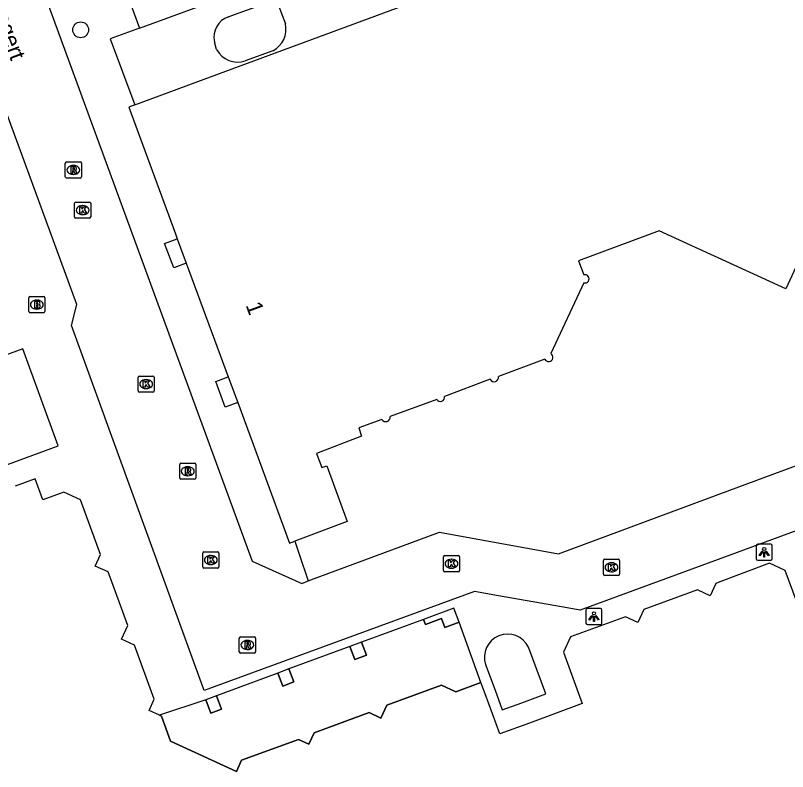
# Model space of a CAD drawing. Extents: x 160806 to 161707, y 383697 to 384148.
# Drawn here: x 160956.33 to 161004.31, y 383874.79 to 383921.78 of the extents above; entities that cross this region are included whole.
import ezdxf

# ---------------------------------------------------------------- set-up
doc = ezdxf.new("R2010")
doc.units = 0
for name, color, linetype in [('IMGEO_Boom', 7, 'Continuous'), ('IMGEO_Brandkraan', 7, 'Continuous'), ('IMGEO_Kolk', 7, 'Continuous'), ('IMGEO_Lichtpunt', 7, 'Continuous'), ('IMGEO_Openbare_ruimte_label', 7, 'Continuous'), ('IMGEO_Pand', 7, 'Continuous'), ('IMGEO_Pand_nummerreeks', 7, 'Continuous'), ('IMGEO_Pand_overbouw', 7, 'Continuous'), ('IMGEO_Rijbaan_lokaal_open', 7, 'Continuous'), ('IMGEO_Rioolput', 7, 'Continuous'), ('IMGEO_Voetpad_open', 7, 'Continuous')]:
    doc.layers.add(name, color=color, linetype=linetype)

msp = doc.modelspace()

# ---------------------------------------------------------------- linework, layer by layer
at = {"layer": 'IMGEO_Boom'}
msp.add_circle((160960.386, 383920.883), 0.489, dxfattribs=at)
at = {"layer": 'IMGEO_Brandkraan'}
for p, q in [((160957.236, 383904.306), (160958.088, 383904.306)), ((160957.161, 383903.38), (160957.161, 383904.232)), ((160957.649, 383904.086), (160957.674, 383904.086)), ((160958.162, 383904.232), (160958.162, 383903.38)), ((160958.088, 383903.306), (160957.236, 383903.306)), ((160957.672, 383903.526), (160957.647, 383903.526))]:
    msp.add_line(p, q, dxfattribs=at)
for points in [[(160957.236, 383904.306), (160958.088, 383904.306)], [(160957.161, 383903.38), (160957.161, 383904.232)], [(160957.509, 383904.006), (160957.509, 383903.606), (160957.722, 383903.606)], [(160957.74, 383904.006), (160957.509, 383904.006)], [(160957.688, 383903.925), (160957.634, 383903.925), (160957.634, 383903.849)], [(160957.634, 383903.849), (160957.687, 383903.849)], [(160958.162, 383904.232), (160958.162, 383903.38)], [(160958.088, 383903.306), (160957.236, 383903.306)], [(160957.696, 383903.773), (160957.634, 383903.773), (160957.634, 383903.692)], [(160957.634, 383903.692), (160957.696, 383903.692)]]:
    msp.add_lwpolyline(points, dxfattribs=at)
for centre, radius, start, end in [((160957.238, 383904.23), 0.0765, 91.552, 178.448), ((160957.238, 383904.23), 0.0765, 91.552, 178.448), ((160958.086, 383904.23), 0.0765, 1.552, 88.448), ((160958.086, 383904.23), 0.0765, 1.552, 88.448), ((160957.689, 383903.887), 0.0379, 267.8285, 90.9355), ((160957.744, 383903.861), 0.145, 59.4692, 91.5367), ((160957.769, 383903.908), 0.0922, 285.5137, 58.1501), ((160957.774, 383903.716), 0.105, 301.3115, 78.989), ((160957.238, 383903.382), 0.0765, 181.552, 268.448), ((160957.238, 383903.382), 0.0765, 181.552, 268.448), ((160957.697, 383903.732), 0.0404, 269.8759, 90.5077), ((160957.728, 383903.857), 0.251, 268.6676, 293.5347), ((160958.086, 383903.382), 0.0765, 271.552, 358.448), ((160958.086, 383903.382), 0.0765, 271.552, 358.448)]:
    msp.add_arc(centre, radius, start, end, dxfattribs=at)
for centre, major_axis, ratio, start_param, end_param in [((160957.648, 383903.806), (-0.387, 0.002), 0.722429, 4.712389, 7.853982), ((160957.673, 383903.806), (-0.39, 0.002), 0.717154, 1.570796, 4.712389)]:
    msp.add_ellipse(centre, major_axis=major_axis, ratio=ratio, start_param=start_param, end_param=end_param, dxfattribs=at)
at = {"layer": 'IMGEO_Kolk'}
for p, q in [((160960.006, 383909.256), (160960.006, 383910.108)), ((160960.081, 383910.182), (160960.933, 383910.182)), ((160961.007, 383910.108), (160961.007, 383909.256)), ((160960.494, 383909.962), (160960.519, 383909.962)), ((160960.933, 383909.182), (160960.081, 383909.182)), ((160960.517, 383909.402), (160960.492, 383909.402)), ((160963.952, 383898.443), (160963.952, 383899.295)), ((160964.027, 383899.369), (160964.879, 383899.369)), ((160964.44, 383899.149), (160964.465, 383899.149)), ((160964.953, 383899.295), (160964.953, 383898.443)), ((160964.463, 383898.589), (160964.438, 383898.589)), ((160964.879, 383898.369), (160964.027, 383898.369)), ((160968.049, 383888.436), (160968.901, 383888.436)), ((160967.974, 383887.51), (160967.974, 383888.362)), ((160968.462, 383888.216), (160968.487, 383888.216)), ((160968.975, 383888.362), (160968.975, 383887.51)), ((160982.931, 383887.281), (160982.931, 383888.133)), ((160983.006, 383888.207), (160983.858, 383888.207)), ((160983.419, 383887.987), (160983.444, 383887.987)), ((160983.932, 383888.133), (160983.932, 383887.281)), ((160992.949, 383887.981), (160993.801, 383887.981)), ((160968.485, 383887.656), (160968.46, 383887.656)), ((160992.874, 383887.055), (160992.874, 383887.907)), ((160993.362, 383887.761), (160993.387, 383887.761)), ((160993.875, 383887.907), (160993.875, 383887.055)), ((160968.901, 383887.436), (160968.049, 383887.436)), ((160983.858, 383887.207), (160983.006, 383887.207)), ((160983.442, 383887.427), (160983.417, 383887.427)), ((160993.385, 383887.201), (160993.36, 383887.201)), ((160993.801, 383886.981), (160992.949, 383886.981))]:
    msp.add_line(p, q, dxfattribs=at)
for points in [[(160960.006, 383909.256), (160960.006, 383910.108)], [(160960.081, 383910.182), (160960.933, 383910.182)], [(160961.007, 383910.108), (160961.007, 383909.256)], [(160960.327, 383909.882), (160960.45, 383909.882), (160960.45, 383909.731), (160960.58, 383909.882), (160960.744, 383909.882), (160960.598, 383909.731), (160960.751, 383909.482), (160960.599, 383909.482), (160960.514, 383909.646), (160960.45, 383909.579), (160960.45, 383909.482), (160960.327, 383909.482), (160960.327, 383909.882)], [(160960.933, 383909.182), (160960.081, 383909.182)], [(160963.952, 383898.443), (160963.952, 383899.295)], [(160964.027, 383899.369), (160964.879, 383899.369)], [(160964.273, 383899.069), (160964.396, 383899.069), (160964.396, 383898.918), (160964.526, 383899.069), (160964.69, 383899.069), (160964.544, 383898.918), (160964.697, 383898.669), (160964.545, 383898.669), (160964.46, 383898.833), (160964.396, 383898.766), (160964.396, 383898.669), (160964.273, 383898.669), (160964.273, 383899.069)], [(160964.953, 383899.295), (160964.953, 383898.443)], [(160964.879, 383898.369), (160964.027, 383898.369)], [(160968.049, 383888.436), (160968.901, 383888.436)], [(160967.974, 383887.51), (160967.974, 383888.362)], [(160968.295, 383888.136), (160968.418, 383888.136), (160968.418, 383887.985), (160968.548, 383888.136), (160968.712, 383888.136), (160968.566, 383887.985), (160968.719, 383887.736), (160968.567, 383887.736), (160968.482, 383887.9), (160968.418, 383887.833), (160968.418, 383887.736), (160968.295, 383887.736), (160968.295, 383888.136)], [(160968.975, 383888.362), (160968.975, 383887.51)], [(160982.931, 383887.281), (160982.931, 383888.133)], [(160983.006, 383888.207), (160983.858, 383888.207)], [(160983.932, 383888.133), (160983.932, 383887.281)], [(160992.949, 383887.981), (160993.801, 383887.981)], [(160983.252, 383887.907), (160983.375, 383887.907), (160983.375, 383887.756), (160983.505, 383887.907), (160983.669, 383887.907), (160983.523, 383887.756), (160983.676, 383887.507), (160983.524, 383887.507), (160983.439, 383887.671), (160983.375, 383887.604), (160983.375, 383887.507), (160983.252, 383887.507), (160983.252, 383887.907)], [(160992.874, 383887.055), (160992.874, 383887.907)], [(160993.195, 383887.681), (160993.318, 383887.681), (160993.318, 383887.53), (160993.448, 383887.681), (160993.612, 383887.681), (160993.466, 383887.53), (160993.619, 383887.281), (160993.467, 383887.281), (160993.382, 383887.445), (160993.318, 383887.378), (160993.318, 383887.281), (160993.195, 383887.281), (160993.195, 383887.681)], [(160993.875, 383887.907), (160993.875, 383887.055)], [(160968.901, 383887.436), (160968.049, 383887.436)], [(160983.858, 383887.207), (160983.006, 383887.207)], [(160993.801, 383886.981), (160992.949, 383886.981)]]:
    msp.add_lwpolyline(points, dxfattribs=at)
for centre, start, end in [((160960.083, 383910.106), 91.552, 178.448), ((160960.083, 383910.106), 91.552, 178.448), ((160960.931, 383910.106), 1.552, 88.448), ((160960.931, 383910.106), 1.552, 88.448), ((160960.083, 383909.258), 181.552, 268.448), ((160960.083, 383909.258), 181.552, 268.448), ((160960.931, 383909.258), 271.552, 358.448), ((160960.931, 383909.258), 271.552, 358.448), ((160964.029, 383899.293), 91.552, 178.448), ((160964.029, 383899.293), 91.552, 178.448), ((160964.877, 383899.293), 1.552, 88.448), ((160964.877, 383899.293), 1.552, 88.448), ((160964.029, 383898.445), 181.552, 268.448), ((160964.029, 383898.445), 181.552, 268.448), ((160964.877, 383898.445), 271.552, 358.448), ((160964.877, 383898.445), 271.552, 358.448), ((160968.051, 383888.36), 91.552, 178.448), ((160968.051, 383888.36), 91.552, 178.448), ((160968.899, 383888.36), 1.552, 88.448), ((160968.899, 383888.36), 1.552, 88.448), ((160983.008, 383888.131), 91.552, 178.448), ((160983.008, 383888.131), 91.552, 178.448), ((160983.856, 383888.131), 1.552, 88.448), ((160983.856, 383888.131), 1.552, 88.448), ((160992.951, 383887.905), 91.552, 178.448), ((160992.951, 383887.905), 91.552, 178.448), ((160993.799, 383887.905), 1.552, 88.448), ((160993.799, 383887.905), 1.552, 88.448), ((160968.051, 383887.512), 181.552, 268.448), ((160968.051, 383887.512), 181.552, 268.448), ((160968.899, 383887.512), 271.552, 358.448), ((160968.899, 383887.512), 271.552, 358.448), ((160983.008, 383887.283), 181.552, 268.448), ((160983.008, 383887.283), 181.552, 268.448), ((160983.856, 383887.283), 271.552, 358.448), ((160983.856, 383887.283), 271.552, 358.448), ((160992.951, 383887.057), 181.552, 268.448), ((160992.951, 383887.057), 181.552, 268.448), ((160993.799, 383887.057), 271.552, 358.448), ((160993.799, 383887.057), 271.552, 358.448)]:
    msp.add_arc(centre, 0.0765, start, end, dxfattribs=at)
for centre, major_axis, ratio, start_param, end_param in [((160960.493, 383909.682), (-0.387, 0.002), 0.722429, 4.712389, 7.853982), ((160960.518, 383909.682), (-0.39, 0.002), 0.717154, 1.570796, 4.712389), ((160964.439, 383898.869), (-0.387, 0.002), 0.722429, 4.712389, 7.853982), ((160964.464, 383898.869), (-0.39, 0.002), 0.717154, 1.570796, 4.712389), ((160968.461, 383887.936), (-0.387, 0.002), 0.722429, 4.712389, 7.853982), ((160968.486, 383887.936), (-0.39, 0.002), 0.717154, 1.570796, 4.712389), ((160983.418, 383887.707), (-0.387, 0.002), 0.722429, 4.712389, 7.853982), ((160983.443, 383887.707), (-0.39, 0.002), 0.717154, 1.570796, 4.712389), ((160993.361, 383887.481), (-0.387, 0.002), 0.722429, 4.712389, 7.853982), ((160993.386, 383887.481), (-0.39, 0.002), 0.717154, 1.570796, 4.712389)]:
    msp.add_ellipse(centre, major_axis=major_axis, ratio=ratio, start_param=start_param, end_param=end_param, dxfattribs=at)
at = {"layer": 'IMGEO_Lichtpunt'}
for p, q in [((161003.268, 383888.913), (161002.46, 383888.913)), ((161003.268, 383888.913), (161002.46, 383888.913)), ((161002.366, 383888.818), (161002.366, 383888.011)), ((161002.366, 383888.818), (161002.366, 383888.011)), ((161003.362, 383888.011), (161003.362, 383888.818)), ((161003.362, 383888.011), (161003.362, 383888.818)), ((161002.46, 383887.917), (161003.268, 383887.917)), ((161002.46, 383887.917), (161003.268, 383887.917)), ((160991.783, 383884.828), (160991.783, 383884.021)), ((160991.783, 383884.828), (160991.783, 383884.021)), ((160992.685, 383884.923), (160991.877, 383884.923)), ((160992.685, 383884.923), (160991.877, 383884.923)), ((160992.779, 383884.021), (160992.779, 383884.828)), ((160992.779, 383884.021), (160992.779, 383884.828)), ((160991.877, 383883.927), (160992.685, 383883.927)), ((160991.877, 383883.927), (160992.685, 383883.927))]:
    msp.add_line(p, q, dxfattribs=at)
for points in [[(161002.74, 383888.482), (161002.779, 383888.454), (161002.591, 383888.192), (161002.553, 383888.219), (161002.74, 383888.482)], [(161002.842, 383888.434), (161002.889, 383888.434), (161002.889, 383888.112), (161002.842, 383888.112), (161002.842, 383888.434)], [(161002.952, 383888.454), (161002.99, 383888.481), (161003.177, 383888.219), (161003.138, 383888.191), (161002.952, 383888.454)], [(160992.157, 383884.492), (160992.196, 383884.464), (160992.008, 383884.202), (160991.97, 383884.229), (160992.157, 383884.492)], [(160992.259, 383884.444), (160992.306, 383884.444), (160992.306, 383884.122), (160992.259, 383884.122), (160992.259, 383884.444)], [(160992.369, 383884.464), (160992.407, 383884.491), (160992.594, 383884.229), (160992.555, 383884.201), (160992.369, 383884.464)]]:
    msp.add_lwpolyline(points, dxfattribs=at)
for centre in [(161002.865, 383888.616), (160992.282, 383884.626)]:
    msp.add_circle(centre, 0.0994, dxfattribs=at)
for centre, start, end in [((161002.46, 383888.818), 90, 180), ((161002.46, 383888.818), 90, 180), ((161003.268, 383888.818), 0, 90), ((161003.268, 383888.818), 0, 90), ((161002.46, 383888.011), 180, 270), ((161002.46, 383888.011), 180, 270), ((161003.268, 383888.011), 270, 0), ((161003.268, 383888.011), 270, 360), ((160991.877, 383884.828), 90, 180), ((160991.877, 383884.828), 90, 180), ((160992.685, 383884.828), 0, 90), ((160992.685, 383884.828), 0, 90), ((160991.877, 383884.021), 180, 270), ((160991.877, 383884.021), 180, 270), ((160992.685, 383884.021), 270, 0), ((160992.685, 383884.021), 270, 360)]:
    msp.add_arc(centre, 0.0946, start, end, dxfattribs=at)
at = {"layer": 'IMGEO_Pand'}
for points in [[(160964.049, 383920.98), (160968.743, 383922.704), (160969.3, 383922.908), (160972.116, 383923.943), (160977.173, 383925.8), (160969.36, 383947.074), (160968.633, 383946.807), (160968.457, 383947.286), (160989.798, 383955.124), (160990.551, 383954.776), (160993.927, 383956.015), (160994.304, 383956.829), (160995.097, 383956.462), (160998.389, 383957.671), (160998.749, 383958.448), (161000, 383958.902), (161000.341, 383959.026), (160998.393, 383964.227), (160997.341, 383967.036), (160995.462, 383972.051)], [(160975.504, 383964.664), (160963.59, 383960.254), (160964.46, 383957.905), (160963.873, 383957.689), (160963.583, 383958.479), (160958.126, 383956.475), (160958.56, 383955.294), (160955.925, 383954.326), (160957.713, 383949.459), (160956.787, 383949.119), (160958.794, 383943.656), (160959.589, 383943.948), (160959.797, 383943.383), (160956.293, 383942.096), (160964.049, 383920.98)], [(160963.751, 383916.221), (160968.062, 383917.812), (160980.975, 383922.577), (160990.19, 383942.611), (161000, 383938.112), (161001.835, 383937.27), (161002.526, 383938.756), (161003.399, 383939.03), (161004.802, 383938.387), (161005.121, 383937.543), (161004.448, 383936.067), (161016.1, 383930.706), (161006.3, 383909.334), (161004.216, 383904.789), (161003.7, 383905.021), (161000, 383906.721), (160998.375, 383907.467), (160996.345, 383908.4), (160991.322, 383906.532), (160991.646, 383905.654)], [(160969.576, 383921.7), (160969.724, 383921.754), (160972.541, 383922.786), (160973.107, 383921.247)], [(160968.834, 383919.66), (160968.697, 383920.138)], [(160972.334, 383919.588), (160970.613, 383918.956)], [(160963.751, 383916.221), (160963.371, 383916.081), (160966.281, 383908.197), (160966.389, 383907.903)], [(160966.389, 383907.903), (160966.95, 383906.383)], [(160966.95, 383906.383), (160969.561, 383899.31)], [(160991.657, 383905.16), (160989.606, 383900.762)], [(160955.83, 383893.878), (160958.991, 383895.039), (160956.781, 383901.058), (160953.618, 383899.896)], [(160989.233, 383900.425), (160986.352, 383899.331)], [(160969.561, 383899.31), (160970.15, 383897.715)], [(160985.842, 383899.173), (160983.003, 383898.105)], [(160970.15, 383897.715), (160973.37, 383888.99), (160973.686, 383889.108)], [(160982.509, 383897.914), (160979.624, 383896.845)], [(160979.104, 383896.674), (160977.662, 383896.151), (160977.84, 383895.636), (160975.05, 383894.563), (160975.371, 383893.69), (160975.687, 383893.788), (160976.952, 383890.328), (160973.686, 383889.108)], [(160965.28, 383878.291), (160964.635, 383878.589), (160964.957, 383879.283), (160963.726, 383882.635), (160962.916, 383883.01), (160963.309, 383883.858), (160962.084, 383887.193), (160961.29, 383887.56), (160961.624, 383888.283), (160960.382, 383891.667), (160959.339, 383892.15), (160958.04, 383891.673), (160957.559, 383892.984), (160956.324, 383892.531)], [(161005.328, 383884.163), (161004.162, 383887.291), (161003.189, 383887.736), (161000, 383886.534), (160999.864, 383886.483), (160999.509, 383885.715), (160998.726, 383886.077), (160995.39, 383884.852), (160995.019, 383884.051), (160994.244, 383884.41), (160990.82, 383883.153), (160990.384, 383882.209), (160991.559, 383879.009), (160988.268, 383877.801), (160986.425, 383877.124), (160985.512, 383879.611), (160985.251, 383880.322)], [(160983.899, 383884.082), (160983.573, 383884.95), (160981.685, 383884.242)], [(160981.685, 383884.242), (160981.806, 383883.919), (160982.801, 383884.293), (160983.006, 383883.747), (160983.899, 383884.082)], [(160977.843, 383882.826), (160977.115, 383882.553)], [(160977.115, 383882.553), (160977.417, 383881.746), (160978.146, 383882.019), (160977.843, 383882.826)], [(160985.549, 383881.437), (160986.135, 383879.839), (160986.583, 383878.619), (160987.803, 383879.067), (160989.284, 383879.611), (160988.217, 383882.517)], [(160973.326, 383881.166), (160972.645, 383880.91)], [(160972.645, 383880.91), (160972.947, 383880.105), (160973.628, 383880.361), (160973.326, 383881.166)], [(160985.251, 383880.322), (160983.694, 383879.75), (160982.817, 383880.156), (160979.408, 383878.905), (160979.043, 383878.115), (160978.314, 383878.452), (160974.904, 383877.2), (160974.572, 383876.482), (160973.913, 383876.786), (160970.387, 383875.492), (160970.062, 383874.789), (160965.973, 383876.682), (160965.403, 383878.234), (160965.28, 383878.291)], [(160968.826, 383879.503), (160968.16, 383879.253)], [(160968.16, 383879.253), (160968.473, 383878.417), (160969.14, 383878.667), (160968.826, 383879.503)]]:
    msp.add_lwpolyline(points, dxfattribs=at)
for centre, radius, start, end in [((160970.009, 383920.428), 1.344, 108.7966, 192.4669), ((160971.634, 383920.924), 1.508, 297.66, 12.3743), ((160970.146, 383920.375), 1.494, 208.6063, 288.2135), ((160991.722, 383905.409), 0.257, 255.3238, 107.2275), ((160989.47, 383900.538), 0.262, 205.4142, 58.7805), ((160986.087, 383899.284), 0.269, 204.3448, 10.0816), ((160982.739, 383898.054), 0.269, 211.3304, 10.9465), ((160979.346, 383896.815), 0.28, 210.2325, 6.174), ((160986.919, 383881.889), 1.442, 25.801, 198.2749)]:
    msp.add_arc(centre, radius, start, end, dxfattribs=at)
at = {"layer": 'IMGEO_Pand_overbouw'}
msp.add_lwpolyline([(160983.899, 383884.082), (160983.006, 383883.747), (160982.801, 383884.293), (160981.806, 383883.919), (160981.685, 383884.242), (160977.843, 383882.826), (160978.146, 383882.019), (160977.417, 383881.746), (160977.115, 383882.553), (160973.326, 383881.166), (160973.628, 383880.361), (160972.947, 383880.105), (160972.645, 383880.91), (160968.826, 383879.503), (160969.14, 383878.667), (160968.473, 383878.417), (160968.16, 383879.253), (160965.28, 383878.291), (160965.403, 383878.234), (160965.973, 383876.682), (160970.062, 383874.789), (160970.387, 383875.492), (160973.913, 383876.786), (160974.572, 383876.482), (160974.904, 383877.2), (160978.314, 383878.452), (160979.043, 383878.115), (160979.408, 383878.905), (160982.817, 383880.156), (160983.694, 383879.75), (160985.251, 383880.322)], close=True, dxfattribs=at)
at = {"layer": 'IMGEO_Rijbaan_lokaal_open'}
for points in [[(160947.428, 383954.476), (160947.548, 383951.917), (160971.037, 383887.859), (160974.125, 383886.483), (160974.531, 383886.634)], [(161034.783, 383900.781), (161000, 383887.972), (160991.432, 383884.817), (160990.275, 383885.032), (160986.341, 383885.715), (160984.869, 383885.974), (160968.05, 383879.828), (160959.806, 383902.516), (160960.137, 383903.811), (160950.161, 383931.007)], [(160974.531, 383886.634), (160982.677, 383889.672), (160990.074, 383888.326), (161000, 383892.005), (161033.437, 383904.394)]]:
    msp.add_lwpolyline(points, dxfattribs=at)
at = {"layer": 'IMGEO_Rioolput'}
for p, q in [((160959.431, 383911.75), (160959.431, 383912.602)), ((160959.506, 383912.676), (160960.358, 383912.676)), ((160959.919, 383912.456), (160959.944, 383912.456)), ((160960.432, 383912.602), (160960.432, 383911.75)), ((160960.358, 383911.676), (160959.506, 383911.676)), ((160959.942, 383911.896), (160959.917, 383911.896)), ((160966.54, 383893.026), (160966.54, 383893.878)), ((160966.615, 383893.952), (160967.467, 383893.952)), ((160967.028, 383893.732), (160967.053, 383893.732)), ((160967.541, 383893.878), (160967.541, 383893.026)), ((160967.467, 383892.952), (160966.615, 383892.952)), ((160967.051, 383893.172), (160967.026, 383893.172)), ((160970.319, 383883.155), (160971.171, 383883.155)), ((160970.244, 383882.229), (160970.244, 383883.081)), ((160970.732, 383882.935), (160970.757, 383882.935)), ((160971.245, 383883.081), (160971.245, 383882.229)), ((160970.755, 383882.375), (160970.73, 383882.375)), ((160971.171, 383882.155), (160970.319, 383882.155))]:
    msp.add_line(p, q, dxfattribs=at)
for points in [[(160959.431, 383911.75), (160959.431, 383912.602)], [(160959.506, 383912.676), (160960.358, 383912.676)], [(160960.432, 383912.602), (160960.432, 383911.75)], [(160960.02, 383912.374), (160959.768, 383912.376), (160959.768, 383911.976)], [(160959.768, 383911.976), (160959.892, 383911.976), (160959.892, 383912.138), (160959.903, 383912.138)], [(160959.946, 383912.295), (160959.892, 383912.295), (160959.892, 383912.214)], [(160959.892, 383912.214), (160959.944, 383912.214)], [(160959.95, 383912.109), (160960.021, 383911.976), (160960.161, 383911.976), (160960.096, 383912.102)], [(160960.358, 383911.676), (160959.506, 383911.676)], [(160966.54, 383893.026), (160966.54, 383893.878)], [(160966.615, 383893.952), (160967.467, 383893.952)], [(160967.541, 383893.878), (160967.541, 383893.026)], [(160967.129, 383893.65), (160966.877, 383893.652), (160966.877, 383893.252)], [(160966.877, 383893.252), (160967.001, 383893.252), (160967.001, 383893.414), (160967.012, 383893.414)], [(160967.055, 383893.571), (160967.001, 383893.571), (160967.001, 383893.49)], [(160967.001, 383893.49), (160967.053, 383893.49)], [(160967.059, 383893.385), (160967.13, 383893.252), (160967.27, 383893.252), (160967.205, 383893.378)], [(160967.467, 383892.952), (160966.615, 383892.952)], [(160970.319, 383883.155), (160971.171, 383883.155)], [(160970.244, 383882.229), (160970.244, 383883.081)], [(160970.833, 383882.853), (160970.581, 383882.855), (160970.581, 383882.455)], [(160970.759, 383882.774), (160970.705, 383882.774), (160970.705, 383882.693)], [(160970.705, 383882.693), (160970.757, 383882.693)], [(160971.245, 383883.081), (160971.245, 383882.229)], [(160970.581, 383882.455), (160970.705, 383882.455), (160970.705, 383882.617), (160970.716, 383882.617)], [(160970.763, 383882.588), (160970.834, 383882.455), (160970.974, 383882.455), (160970.909, 383882.581)], [(160971.171, 383882.155), (160970.319, 383882.155)]]:
    msp.add_lwpolyline(points, dxfattribs=at)
for centre, radius, start, end in [((160959.508, 383912.6), 0.0765, 91.552, 178.448), ((160959.508, 383912.6), 0.0765, 91.552, 178.448), ((160960.356, 383912.6), 0.0765, 1.552, 88.448), ((160960.356, 383912.6), 0.0765, 1.552, 88.448), ((160959.902, 383912.085), 0.0533, 26.0293, 88.6989), ((160959.928, 383912.403), 0.19, 274.7715, 282.9687), ((160959.952, 383912.199), 0.0964, 77.0061, 93.1865), ((160959.966, 383912.256), 0.0378, 276.6634, 79.6772), ((160960.019, 383912.264), 0.109, 350.3612, 89.416), ((160960.017, 383912.264), 0.112, 277.5842, 350.9817), ((160960.001, 383912.049), 0.108, 29.5134, 73.7905), ((160959.508, 383911.752), 0.0765, 181.552, 268.448), ((160959.508, 383911.752), 0.0765, 181.552, 268.448), ((160960.356, 383911.752), 0.0765, 271.552, 358.448), ((160960.356, 383911.752), 0.0765, 271.552, 358.448), ((160966.617, 383893.876), 0.0765, 91.552, 178.448), ((160966.617, 383893.876), 0.0765, 91.552, 178.448), ((160967.465, 383893.876), 0.0765, 1.552, 88.448), ((160967.465, 383893.876), 0.0765, 1.552, 88.448), ((160967.011, 383893.361), 0.0533, 26.0293, 88.6989), ((160967.037, 383893.679), 0.19, 274.7715, 282.9687), ((160967.061, 383893.475), 0.0964, 77.0061, 93.1865), ((160967.075, 383893.532), 0.0378, 276.6634, 79.6772), ((160967.128, 383893.54), 0.109, 350.3612, 89.416), ((160967.126, 383893.54), 0.112, 277.5842, 350.9817), ((160967.11, 383893.325), 0.108, 29.5134, 73.7905), ((160966.617, 383893.028), 0.0765, 181.552, 268.448), ((160966.617, 383893.028), 0.0765, 181.552, 268.448), ((160967.465, 383893.028), 0.0765, 271.552, 358.448), ((160967.465, 383893.028), 0.0765, 271.552, 358.448), ((160970.321, 383883.079), 0.0765, 91.552, 178.448), ((160970.321, 383883.079), 0.0765, 91.552, 178.448), ((160971.169, 383883.079), 0.0765, 1.552, 88.448), ((160971.169, 383883.079), 0.0765, 1.552, 88.448), ((160970.741, 383882.882), 0.19, 274.7715, 282.9687), ((160970.765, 383882.678), 0.0964, 77.0061, 93.1865), ((160970.779, 383882.735), 0.0378, 276.6634, 79.6772), ((160970.832, 383882.743), 0.109, 350.3612, 89.416), ((160970.83, 383882.743), 0.112, 277.5842, 350.9817), ((160970.321, 383882.231), 0.0765, 181.552, 268.448), ((160970.321, 383882.231), 0.0765, 181.552, 268.448), ((160970.715, 383882.564), 0.0533, 26.0293, 88.6989), ((160970.814, 383882.528), 0.108, 29.5134, 73.7905), ((160971.169, 383882.231), 0.0765, 271.552, 358.448), ((160971.169, 383882.231), 0.0765, 271.552, 358.448)]:
    msp.add_arc(centre, radius, start, end, dxfattribs=at)
for centre, major_axis, ratio, start_param, end_param in [((160959.918, 383912.176), (-0.387, 0.002), 0.722429, 4.712389, 7.853982), ((160959.943, 383912.176), (-0.39, 0.002), 0.717154, 1.570796, 4.712389), ((160967.027, 383893.452), (-0.387, 0.002), 0.722429, 4.712389, 7.853982), ((160967.052, 383893.452), (-0.39, 0.002), 0.717154, 1.570796, 4.712389), ((160970.731, 383882.655), (-0.387, 0.002), 0.722429, 4.712389, 7.853982), ((160970.756, 383882.655), (-0.39, 0.002), 0.717154, 1.570796, 4.712389)]:
    msp.add_ellipse(centre, major_axis=major_axis, ratio=ratio, start_param=start_param, end_param=end_param, dxfattribs=at)
at = {"layer": 'IMGEO_Voetpad_open'}
for points in [[(160964.049, 383920.98), (160962.214, 383920.319), (160963.751, 383916.221)], [(160966.95, 383906.383), (160966.166, 383906.094), (160965.605, 383907.614), (160966.389, 383907.903)], [(160970.15, 383897.715), (160969.371, 383897.428), (160968.781, 383899.023), (160969.561, 383899.31)], [(160973.686, 383889.108), (160973.964, 383888.294), (160974.531, 383886.634)], [(160981.685, 383884.242), (160977.843, 383882.826)], [(160985.251, 383880.322), (160983.899, 383884.082)], [(160977.115, 383882.553), (160973.326, 383881.166)], [(160972.645, 383880.91), (160968.826, 383879.503)], [(160968.16, 383879.253), (160965.28, 383878.291)]]:
    msp.add_lwpolyline(points, dxfattribs=at)

# ---------------------------------------------------------------- texts
at = {"layer": 'IMGEO_Openbare_ruimte_label'}
msp.add_text('Bogert', height=1, rotation=290.1202, dxfattribs=at).set_placement((160954.705, 383922.619))
at = {"layer": 'IMGEO_Pand_nummerreeks'}
msp.add_text('1', height=1, rotation=290.2455, dxfattribs=at).set_placement((160970.629, 383903.77))

doc.saveas('drawing.dxf')
